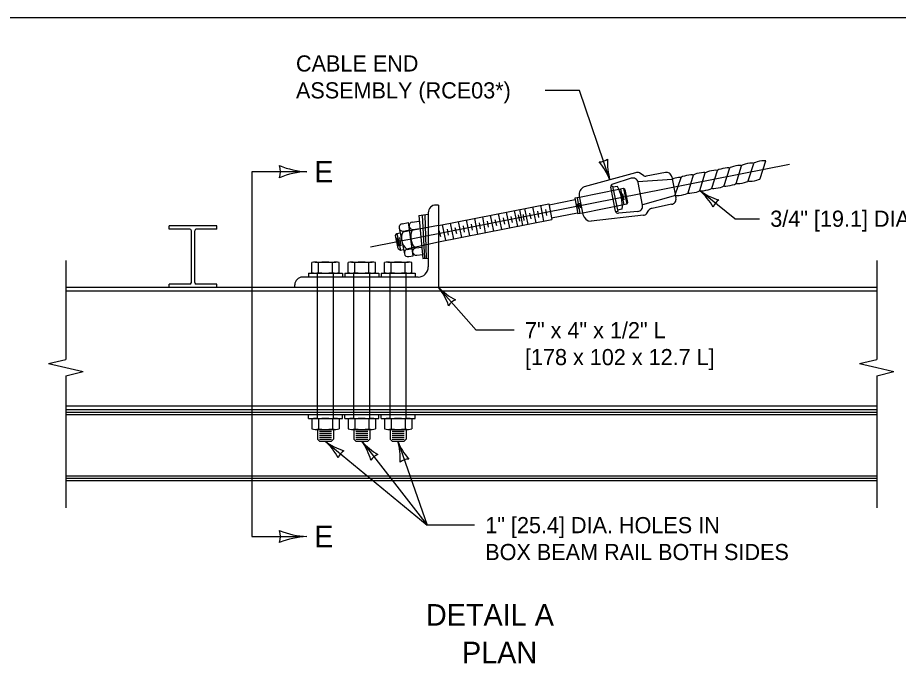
# Model space of a CAD drawing. Extents: x 49991.4 to 50021, y 49987.6 to 50011.4.
# Drawn here: x 50009.364 to 50012.637, y 49996.55 to 49998.999 of the extents above; entities that cross this region are included whole.
import ezdxf

# ---------------------------------------------------------------- set-up
doc = ezdxf.new("R2010")
doc.units = 0
for name, color, linetype in [('Level 1', 7, 'Continuous'), ('Level 2', 7, 'Continuous'), ('Level 3', 7, 'Continuous'), ('Level 4', 7, 'Continuous'), ('Level 5', 7, 'Continuous'), ('Level 6', 7, 'Continuous')]:
    doc.layers.add(name, color=color, linetype=linetype)

msp = doc.modelspace()

# ---------------------------------------------------------------- linework, layer by layer
at = {"layer": 'Level 1'}
for p, q in [((50012.1234, 49998.4006), (50012.1441, 49998.466)), ((50011.9434, 49998.3651), (50011.9639, 49998.4304)), ((50012.0091, 49998.4397), (50011.9884, 49998.3739)), ((50012.0334, 49998.3828), (50012.0541, 49998.4482)), ((50012.0784, 49998.3917), (50012.0991, 49998.4571)), ((50011.6593, 49998.4216), (50011.4693, 49998.3696)), ((50011.6436, 49998.4017), (50011.575, 49998.3804)), ((50011.6913, 49998.4111), (50011.6747, 49998.4222)), ((50011.7707, 49998.4233), (50011.6991, 49998.409)), ((50011.7944, 49998.4073), (50011.81, 49998.3285)), ((50011.8077, 49998.3399), (50011.829, 49998.4042)), ((50011.8738, 49998.4134), (50011.8537, 49998.3469)), ((50011.8984, 49998.3562), (50011.9192, 49998.422)), ((50011.5748, 49998.3728), (50011.5679, 49998.3714)), ((50011.5859, 49998.2796), (50011.5681, 49998.3689)), ((50011.5748, 49998.3728), (50011.5943, 49998.2787)), ((50011.593, 49998.3717), (50011.5757, 49998.3683)), ((50011.6156, 49998.3632), (50011.5984, 49998.3598)), ((50011.6199, 49998.3603), (50011.6156, 49998.3632)), ((50011.6156, 49998.3632), (50011.6281, 49998.3051)), ((50011.686, 49998.302), (50011.6693, 49998.3864)), ((50011.4516, 49998.3307), (50011.4348, 49998.3274)), ((50011.4506, 49998.3356), (50011.4647, 49998.2666)), ((50011.6038, 49998.3607), (50011.6163, 49998.3029)), ((50011.6121, 49998.3441), (50011.617, 49998.3212)), ((50011.6199, 49998.3603), (50011.6306, 49998.3111)), ((50010.9279, 49998.3022), (50010.9183, 49998.3022)), ((50010.9279, 49998.2263), (50011.3373, 49998.3072)), ((50010.9279, 49998.3022), (50010.9279, 49997.9962)), ((50011.3068, 49998.3012), (50011.3185, 49998.242)), ((50011.3373, 49998.3072), (50011.3489, 49998.2481)), ((50011.4358, 49998.322), (50011.3384, 49998.3018)), ((50011.4348, 49998.3274), (50011.4454, 49998.269)), ((50011.4433, 49998.3077), (50011.448, 49998.289)), ((50011.4544, 49998.2708), (50011.4438, 49998.3292)), ((50011.4523, 49998.3094), (50011.4558, 49998.2915)), ((50011.6281, 49998.3051), (50011.6108, 49998.3017)), ((50011.6306, 49998.3111), (50011.6281, 49998.3051)), ((50011.7941, 49998.3049), (50011.7219, 49998.2898)), ((50010.8544, 49998.2636), (50010.8897, 49998.2678)), ((50010.8666, 49998.265), (50010.8756, 49998.1039)), ((50010.8776, 49998.2663), (50010.8824, 49998.1041)), ((50010.8898, 49998.2737), (50010.8898, 49998.0724)), ((50010.8898, 49998.2678), (50010.8898, 49998.1043)), ((50011.15, 49998.2702), (50011.1616, 49998.211)), ((50011.1795, 49998.276), (50011.1912, 49998.2169)), ((50011.2091, 49998.2819), (50011.2217, 49998.2229)), ((50011.2236, 49998.2652), (50011.2282, 49998.2419)), ((50011.2288, 49998.2858), (50011.2396, 49998.2265)), ((50011.2418, 49998.2669), (50011.2454, 49998.2444)), ((50011.2477, 49998.2895), (50011.2593, 49998.2303)), ((50011.2659, 49998.2726), (50011.2712, 49998.2504)), ((50011.2772, 49998.2953), (50011.2898, 49998.2364)), ((50011.2953, 49998.2793), (50011.2999, 49998.256)), ((50011.3258, 49998.2853), (50011.3293, 49998.2628)), ((50011.4448, 49998.2726), (50011.3479, 49998.2534)), ((50011.4635, 49998.2726), (50011.4454, 49998.269)), ((50011.5943, 49998.2787), (50011.5866, 49998.2772)), ((50011.6106, 49998.2867), (50011.5934, 49998.2833)), ((50011.668, 49998.2781), (50011.5967, 49998.2715)), ((50011.7004, 49998.2694), (50011.7096, 49998.283)), ((50010.7924, 49998.2322), (50010.8167, 49998.237)), ((50010.8333, 49998.1138), (50010.8167, 49998.237)), ((50010.8303, 49998.2387), (50010.8564, 49998.2422)), ((50010.8544, 49998.2636), (50010.8692, 49998.1037)), ((50010.9279, 49998.1648), (50011.3489, 49998.2481)), ((50010.9716, 49998.235), (50010.9833, 49998.1758)), ((50011.0012, 49998.2408), (50011.0137, 49998.1818)), ((50011.0307, 49998.2466), (50011.0424, 49998.1875)), ((50011.0612, 49998.2527), (50011.0729, 49998.1935)), ((50011.0784, 49998.2365), (50011.083, 49998.2132)), ((50011.0908, 49998.2585), (50011.1016, 49998.1992)), ((50011.1089, 49998.2425), (50011.1124, 49998.22)), ((50011.1204, 49998.2643), (50011.1321, 49998.2052)), ((50011.1375, 49998.2482), (50011.1429, 49998.2259)), ((50011.168, 49998.2542), (50011.1726, 49998.2309)), ((50011.1967, 49998.2599), (50011.202, 49998.2377)), ((50011.6894, 49998.2646), (50011.4946, 49998.2422)), ((50010.1047, 49998.2248), (50009.9271, 49998.2248)), ((50009.9271, 49998.2128), (50009.9271, 49998.2248)), ((50010.0039, 49998.2128), (50009.9271, 49998.2128)), ((50010.0099, 49998.0142), (50010.0099, 49998.2068)), ((50010.0219, 49998.0142), (50010.0219, 49998.2068)), ((50010.1047, 49998.2128), (50010.0279, 49998.2128)), ((50010.1047, 49998.2128), (50010.1047, 49998.2248)), ((50010.7816, 49998.2161), (50010.8009, 49998.1213)), ((50010.7977, 49998.2054), (50010.8204, 49998.2098)), ((50010.834, 49998.2116), (50010.8589, 49998.2149)), ((50010.9296, 49998.2071), (50010.9349, 49998.1849)), ((50010.942, 49998.2291), (50010.9537, 49998.17)), ((50010.96, 49998.2131), (50010.9636, 49998.1905)), ((50010.9887, 49998.2188), (50010.9941, 49998.1965)), ((50011.0192, 49998.2248), (50011.0238, 49998.2015)), ((50011.0497, 49998.2309), (50011.0532, 49998.2082)), ((50010.7683, 49998.1891), (50010.7733, 49998.1967)), ((50010.7778, 49998.1407), (50010.7683, 49998.1891)), ((50010.7733, 49998.1967), (50010.7851, 49998.199)), ((50010.7733, 49998.1967), (50010.7864, 49998.135)), ((50010.7807, 49998.1497), (50010.7736, 49998.1809)), ((50010.789, 49998.1504), (50010.7837, 49998.182)), ((50010.7778, 49998.1407), (50010.7864, 49998.135)), ((50010.7864, 49998.135), (50010.7977, 49998.1372)), ((50010.8117, 49998.1374), (50010.8296, 49998.141)), ((50010.8432, 49998.1428), (50010.8653, 49998.1457)), ((50010.817, 49998.1105), (50010.8333, 49998.1138)), ((50010.8468, 49998.1156), (50010.8678, 49998.1184)), ((50010.8692, 49998.1037), (50010.8898, 49998.1043)), ((50010.457, 49998.0514), (50010.457, 49998.088)), ((50010.4698, 49998.0902), (50010.5458, 49998.0902)), ((50010.4822, 49998.0513), (50010.4822, 49998.0881)), ((50010.5334, 49998.0513), (50010.5334, 49998.0881)), ((50010.5586, 49998.0514), (50010.5586, 49998.088)), ((50010.592, 49998.0514), (50010.592, 49998.088)), ((50010.6048, 49998.0902), (50010.6808, 49998.0902)), ((50010.6172, 49998.0513), (50010.6172, 49998.0881)), ((50010.6684, 49998.0513), (50010.6684, 49998.0881)), ((50010.6936, 49998.0514), (50010.6936, 49998.088)), ((50010.727, 49998.0514), (50010.727, 49998.088)), ((50010.7398, 49998.0902), (50010.8158, 49998.0902)), ((50010.7522, 49998.0513), (50010.7522, 49998.0881)), ((50010.8034, 49998.0513), (50010.8034, 49998.0881)), ((50010.8286, 49998.0514), (50010.8286, 49998.088)), ((50010.445, 49998.0493), (50010.5708, 49998.0493)), ((50010.445, 49998.0493), (50010.445, 49998.0343)), ((50010.5708, 49998.0493), (50010.5708, 49998.0343)), ((50010.58, 49998.0493), (50010.7058, 49998.0493)), ((50010.58, 49998.0493), (50010.58, 49998.0343)), ((50010.7058, 49998.0493), (50010.7058, 49998.0343)), ((50010.715, 49998.0493), (50010.8408, 49998.0493)), ((50010.715, 49998.0493), (50010.715, 49998.0343)), ((50010.8408, 49998.0493), (50010.8408, 49998.0343)), ((50010.0039, 49998.0082), (50009.9271, 49998.0082)), ((50009.9271, 49997.9962), (50009.9271, 49998.0082)), ((50010.1047, 49998.0082), (50010.0279, 49998.0082)), ((50010.1047, 49997.9962), (50010.1047, 49998.0082)), ((50010.3939, 49997.9962), (50010.3939, 49998.0058)), ((50010.8517, 49998.0343), (50010.4224, 49998.0343)), ((50012.556, 49997.9962), (50009.543, 49997.9962)), ((50012.556, 49997.5402), (50009.543, 49997.5402)), ((50012.556, 49997.2762), (50009.543, 49997.2762))]:
    msp.add_line(p, q, dxfattribs=at)
msp.add_lwpolyline([(49999.3835, 49998.9992), (50016.7501, 49998.9992), (50016.7501, 49987.7988), (49999.3835, 49987.7988)], close=True, dxfattribs=at)
for centre, radius, start, end in [((50011.6496, 49998.3825), 0.0202, 11.1741, 107.0803), ((50011.6679, 49998.3994), 0.0239, 73.4581, 110.9758), ((50011.6977, 49998.4192), 0.0103, 231.8958, 277.7889), ((50011.7752, 49998.4044), 0.0194, 8.5896, 103.4983), ((50011.4802, 49998.3415), 0.0302, 111.2677, 191.1741), ((50011.578, 49998.3708), 0.0101, 107.1508, 191.0424), ((50011.4409, 49998.2958), 0.17, 356.9288, 26.5077), ((50010.9183, 49998.2737), 0.0285, 90, 180), ((50011.6661, 49998.2982), 0.0203, 275.5759, 10.819), ((50011.7911, 49998.3241), 0.0194, 278.7928, 13.2099), ((50011.4943, 49998.2725), 0.0302, 191.1741, 270.5545), ((50011.5958, 49998.2815), 0.0101, 191.0393, 275.2819), ((50011.6887, 49998.2811), 0.0165, 272.4861, 314.9673), ((50011.7233, 49998.2727), 0.0171, 94.4838, 142.9949), ((50010.795, 49998.2188), 0.0137, 101.0862, 281.2575), ((50010.8322, 49998.2252), 0.0137, 97.6335, 277.6306), ((50010.0039, 49998.2068), 0.006, 0, 90), ((50010.0279, 49998.2068), 0.006, 90, 180), ((50010.841, 49998.1789), 0.0508, 148.6017, 234.753), ((50010.8848, 49998.1833), 0.0602, 152.0655, 223.0482), ((50010.8144, 49998.124), 0.0137, 101.2848, 281.0635), ((50010.845, 49998.1292), 0.0137, 97.6585, 277.6455), ((50010.8517, 49998.0724), 0.0381, 270, 0), ((50010.0039, 49998.0142), 0.006, 270, 0), ((50010.0279, 49998.0142), 0.006, 180, 270), ((50010.4224, 49998.0058), 0.0285, 90, 180)]:
    msp.add_arc(centre, radius, start, end, dxfattribs=at)
for centre, major_axis, ratio, start_param, end_param in [((50012.1216, 49998.4616), (-0.0225, -0.0044), 0.155406, 3.141593, 6.283185), ((50011.9414, 49998.4257), (-0.0225, -0.0044), 0.155406, 3.190469, 6.091551), ((50011.9866, 49998.4349), (-0.0227, -0.0045), 0.153923, 3.240033, 6.283185), ((50012.0316, 49998.4438), (-0.0225, -0.0044), 0.155406, 3.141593, 6.185749), ((50012.0766, 49998.4527), (-0.0225, -0.0044), 0.155406, 3.142586, 6.283185), ((50011.8125, 49998.4008), (0.0165, 0.0034), 0.140692, 0, 2.948999), ((50011.8515, 49998.4086), (-0.0225, -0.0044), 0.155406, 3.234173, 6.283185), ((50011.8965, 49998.4175), (-0.0227, -0.0045), 0.15408, 3.144636, 6.190605), ((50012.1009, 49998.3962), (0.0225, 0.0044), 0.155406, 3.141593, 6.283185), ((50011.9209, 49998.3606), (0.0225, 0.0044), 0.155406, 3.141593, 6.283185), ((50011.9659, 49998.3695), (0.0225, 0.0044), 0.155406, 3.141593, 6.283185), ((50012.0109, 49998.3784), (0.0225, 0.0044), 0.155406, 3.141593, 6.283185), ((50012.0559, 49998.3873), (0.0225, 0.0044), 0.155406, 3.141593, 6.283185), ((50011.8309, 49998.3428), (0.0229, 0.0045), 0.153003, 3.141593, 6.158276), ((50011.8759, 49998.3517), (0.0225, 0.0044), 0.155406, 3.266502, 6.283185), ((50010.4697, 49998.0743), (0.0254, 0), 0.623816, 1.056847, 2.094396), ((50010.5078, 49998.0268), (0.1016, 0), 0.623816, 1.315951, 1.825641), ((50010.5459, 49998.0743), (0.0254, 0), 0.623816, 1.047198, 2.084746), ((50010.6047, 49998.0743), (0.0254, 0), 0.623816, 1.056847, 2.094396), ((50010.6428, 49998.0268), (0.1016, 0), 0.623816, 1.315951, 1.825641), ((50010.6809, 49998.0743), (0.0254, 0), 0.623816, 1.047198, 2.084746), ((50010.7397, 49998.0743), (0.0254, 0), 0.623816, 1.056847, 2.094396), ((50010.7778, 49998.0268), (0.1016, 0), 0.623816, 1.315951, 1.825641), ((50010.8159, 49998.0743), (0.0254, 0), 0.623816, 1.047198, 2.084746), ((50010.4697, 49998.0651), (0.0254, 0), 0.623816, 4.188789, 5.226338), ((50010.5078, 49998.1126), (0.1016, 0), 0.623816, 4.457545, 4.967235), ((50010.5459, 49998.0651), (0.0254, 0), 0.623816, 4.198439, 5.235988), ((50010.6047, 49998.0651), (0.0254, 0), 0.623816, 4.188789, 5.226338), ((50010.6428, 49998.1126), (0.1016, 0), 0.623816, 4.457545, 4.967235), ((50010.6809, 49998.0651), (0.0254, 0), 0.623816, 4.198439, 5.235988), ((50010.7397, 49998.0651), (0.0254, 0), 0.623816, 4.188789, 5.226338), ((50010.7778, 49998.1126), (0.1016, 0), 0.623816, 4.457545, 4.967235), ((50010.8159, 49998.0651), (0.0254, 0), 0.623816, 4.198439, 5.235988)]:
    msp.add_ellipse(centre, major_axis=major_axis, ratio=ratio, start_param=start_param, end_param=end_param, dxfattribs=at)
at = {"layer": 'Level 3'}
for p, q in [((50011.4516, 49998.7287), (50011.3245, 49998.7287)), ((50011.5648, 49998.3958), (50011.4516, 49998.7287)), ((50012.0292, 49998.2514), (50011.8995, 49998.3553)), ((50012.0292, 49998.2514), (50012.1205, 49998.2514)), ((50011.0672, 49997.8368), (50010.9279, 49997.9962)), ((50011.2091, 49997.8368), (50011.0672, 49997.8368)), ((50010.5069, 49997.424), (50010.8851, 49997.112)), ((50010.6431, 49997.424), (50010.8851, 49997.112)), ((50010.7763, 49997.424), (50010.8851, 49997.112)), ((50011.0616, 49997.112), (50010.8851, 49997.112))]:
    msp.add_line(p, q, dxfattribs=at)
for centre, radius, start, end in [((50011.5235, 49998.5172), 0.0548, 270.9069, 306.6293), ((50011.3574, 49998.3156), 0.2223, 21.1286, 41.3121), ((50011.7888, 49998.4598), 0.233, 176.691, 195.9408), ((50012.0308, 49998.5347), 0.2223, 233.7575, 253.941), ((50011.7452, 49998.1807), 0.233, 29.3199, 48.5697), ((50011.9995, 49998.2754), 0.0548, 123.5359, 159.2582), ((50010.7546, 49997.8569), 0.2223, 18.6103, 38.7938), ((50011.0955, 49998.158), 0.233, 223.9816, 243.2315), ((50011.0122, 49997.8997), 0.0548, 113.2931, 149.0155), ((50010.6412, 49997.6012), 0.2223, 232.8407, 253.0242), ((50010.3499, 49997.2518), 0.233, 28.403, 47.6529), ((50010.813, 49997.5674), 0.2223, 220.1612, 240.3448), ((50010.4522, 49997.2905), 0.233, 15.7236, 34.9735), ((50010.9831, 49997.5058), 0.2223, 201.5833, 221.7668), ((50010.5528, 49997.3583), 0.233, 357.1456, 16.3955), ((50010.6058, 49997.3425), 0.0548, 122.619, 158.3414), ((50010.7217, 49997.3227), 0.0548, 109.9396, 145.6619), ((50010.8185, 49997.303), 0.0548, 91.3616, 127.084)]:
    msp.add_arc(centre, radius, start, end, dxfattribs=at)
at = {"layer": 'Level 4'}
for p, q in [((50011.7964, 49998.3974), (50011.6687, 49998.3888)), ((50011.5984, 49998.3598), (50011.4516, 49998.3307)), ((50011.8082, 49998.3374), (50011.6859, 49998.3024)), ((50011.6108, 49998.3017), (50011.4635, 49998.2726)), ((50010.9279, 49998.2263), (50010.7953, 49998.201)), ((50010.8087, 49998.1397), (50010.9279, 49998.1648)), ((50010.4778, 49997.5087), (50010.4778, 49998.0493)), ((50010.5378, 49997.5087), (50010.5378, 49998.0493)), ((50010.6128, 49997.5087), (50010.6128, 49998.0493)), ((50010.6728, 49997.5087), (50010.6728, 49998.0493)), ((50010.7478, 49997.5087), (50010.7478, 49998.0493)), ((50010.8078, 49997.5087), (50010.8078, 49998.0493)), ((50012.556, 49997.9818), (50009.543, 49997.9818)), ((50012.556, 49997.5546), (50009.543, 49997.5546)), ((50012.556, 49997.5311), (50009.543, 49997.5311)), ((50012.556, 49997.522), (50009.543, 49997.522)), ((50010.445, 49997.5087), (50010.445, 49997.522)), ((50010.5708, 49997.5087), (50010.5708, 49997.522)), ((50010.58, 49997.5087), (50010.58, 49997.522)), ((50010.7058, 49997.5087), (50010.7058, 49997.522)), ((50010.715, 49997.5087), (50010.715, 49997.522)), ((50010.8408, 49997.5087), (50010.8408, 49997.522)), ((50010.445, 49997.5087), (50010.5708, 49997.5087)), ((50010.457, 49997.5066), (50010.457, 49997.4699)), ((50010.4821, 49997.5067), (50010.4821, 49997.4698)), ((50010.5335, 49997.5067), (50010.5335, 49997.4699)), ((50010.5586, 49997.5066), (50010.5586, 49997.4699)), ((50010.58, 49997.5087), (50010.7058, 49997.5087)), ((50010.592, 49997.5066), (50010.592, 49997.4699)), ((50010.6171, 49997.5066), (50010.6171, 49997.4699)), ((50010.6685, 49997.5067), (50010.6685, 49997.4699)), ((50010.6936, 49997.5066), (50010.6936, 49997.4699)), ((50010.715, 49997.5087), (50010.8408, 49997.5087)), ((50010.727, 49997.5066), (50010.727, 49997.4699)), ((50010.7522, 49997.5067), (50010.7522, 49997.4699)), ((50010.8035, 49997.5067), (50010.8035, 49997.4698)), ((50010.8286, 49997.5066), (50010.8286, 49997.4699)), ((50010.4698, 49997.4678), (50010.5458, 49997.4678)), ((50010.4778, 49997.4678), (50010.4778, 49997.4315)), ((50010.4853, 49997.4615), (50010.5303, 49997.4615)), ((50010.4853, 49997.454), (50010.5303, 49997.454)), ((50010.4853, 49997.4465), (50010.5303, 49997.4465)), ((50010.5378, 49997.4678), (50010.5378, 49997.4315)), ((50010.6048, 49997.4678), (50010.6808, 49997.4678)), ((50010.6128, 49997.4678), (50010.6128, 49997.4315)), ((50010.6203, 49997.4615), (50010.6653, 49997.4615)), ((50010.6203, 49997.454), (50010.6653, 49997.454)), ((50010.6203, 49997.4465), (50010.6653, 49997.4465)), ((50010.6728, 49997.4678), (50010.6728, 49997.4315)), ((50010.7398, 49997.4678), (50010.8158, 49997.4678)), ((50010.7478, 49997.4678), (50010.7478, 49997.4315)), ((50010.7553, 49997.4615), (50010.8003, 49997.4615)), ((50010.7553, 49997.454), (50010.8003, 49997.454)), ((50010.7553, 49997.4465), (50010.8003, 49997.4465)), ((50010.8078, 49997.4678), (50010.8078, 49997.4315)), ((50010.4778, 49997.4315), (50010.4853, 49997.424)), ((50010.4853, 49997.439), (50010.5303, 49997.439)), ((50010.4853, 49997.4315), (50010.5303, 49997.4315)), ((50010.4853, 49997.424), (50010.5303, 49997.424)), ((50010.5378, 49997.4315), (50010.5303, 49997.424)), ((50010.6128, 49997.4315), (50010.6203, 49997.424)), ((50010.6203, 49997.439), (50010.6653, 49997.439)), ((50010.6203, 49997.4315), (50010.6653, 49997.4315)), ((50010.6203, 49997.424), (50010.6653, 49997.424)), ((50010.6728, 49997.4315), (50010.6653, 49997.424)), ((50010.7478, 49997.4315), (50010.7553, 49997.424)), ((50010.7553, 49997.439), (50010.8003, 49997.439)), ((50010.7553, 49997.4315), (50010.8003, 49997.4315)), ((50010.7553, 49997.424), (50010.8003, 49997.424)), ((50010.8078, 49997.4315), (50010.8003, 49997.424)), ((50012.556, 49997.2944), (50009.543, 49997.2944)), ((50012.556, 49997.2853), (50009.543, 49997.2853))]:
    msp.add_line(p, q, dxfattribs=at)
for centre, major_axis, start_param, end_param in [((50010.4697, 49997.4929), (0.0254, 0), 1.056847, 2.094396), ((50010.5078, 49997.4453), (0.1016, 0), 1.31595, 1.825641), ((50010.5459, 49997.4929), (0.0254, 0), 1.047198, 2.084746), ((50010.6047, 49997.4929), (0.0254, 0), 1.056847, 2.094396), ((50010.6428, 49997.4453), (0.1016, 0), 1.31595, 1.825641), ((50010.6809, 49997.4929), (0.0254, 0), 1.047198, 2.084746), ((50010.7397, 49997.4929), (0.0254, 0), 1.056847, 2.094396), ((50010.7778, 49997.4453), (0.1016, 0), 1.31595, 1.825641), ((50010.8159, 49997.4929), (0.0254, 0), 1.047198, 2.084746), ((50010.4697, 49997.4837), (0.0254, 0), 4.188789, 5.226338), ((50010.5078, 49997.5312), (0.1016, 0), 4.457545, 4.967234), ((50010.5459, 49997.4837), (0.0254, 0), 4.198439, 5.235988), ((50010.6047, 49997.4837), (0.0254, 0), 4.188789, 5.226338), ((50010.6428, 49997.5312), (0.1016, 0), 4.457545, 4.967234), ((50010.6809, 49997.4837), (0.0254, 0), 4.198439, 5.235988), ((50010.7397, 49997.4837), (0.0254, 0), 4.188789, 5.226338), ((50010.7778, 49997.5312), (0.1016, 0), 4.457545, 4.967234), ((50010.8159, 49997.4837), (0.0254, 0), 4.198439, 5.235988)]:
    msp.add_ellipse(centre, major_axis=major_axis, ratio=0.623816, start_param=start_param, end_param=end_param, dxfattribs=at)
at = {"layer": 'Level 5'}
msp.add_line((50012.2321, 49998.4534), (50010.6749, 49998.1458), dxfattribs=at)
at = {"layer": 'Level 6'}
for p, q in [((50010.4134, 49998.4263), (50010.2347, 49998.4263)), ((50010.2347, 49998.4263), (50010.2347, 49997.0696)), ((50009.543, 49998.0962), (50009.543, 49997.728)), ((50012.556, 49998.0962), (50012.556, 49997.728)), ((50009.4792, 49997.7131), (50009.543, 49997.728)), ((50009.4792, 49997.7131), (50009.543, 49997.6978)), ((50012.4922, 49997.7131), (50012.556, 49997.728)), ((50012.4922, 49997.7131), (50012.556, 49997.6978)), ((50009.543, 49997.6978), (50009.6071, 49997.6827)), ((50009.543, 49997.6674), (50009.6071, 49997.6827)), ((50012.556, 49997.6978), (50012.6201, 49997.6827)), ((50012.556, 49997.6674), (50012.6201, 49997.6827)), ((50009.543, 49997.6674), (50009.543, 49997.1762)), ((50012.556, 49997.6674), (50012.556, 49997.1762)), ((50010.2347, 49997.0696), (50010.4134, 49997.0696))]:
    msp.add_line(p, q, dxfattribs=at)
for centre, radius, start, end in [((50010.2677, 49998.4263), 0.073, 342.1388, 17.8612), ((50010.454, 49998.7366), 0.3107, 247.9228, 267.1727), ((50010.4508, 49998.1301), 0.2964, 92.3605, 112.544), ((50010.2677, 49997.0696), 0.073, 342.1388, 17.8612), ((50010.454, 49997.3799), 0.3107, 247.9228, 267.1727), ((50010.4508, 49996.7734), 0.2964, 92.3605, 112.544)]:
    msp.add_arc(centre, radius, start, end, dxfattribs=at)

# ---------------------------------------------------------------- texts
at = {"layer": 'Level 2'}
for s, p in [('CABLE END ', (50010.3983, 49998.7987)), ('ASSEMBLY (RCE03*)', (50010.3983, 49998.6987))]:
    msp.add_text(s, height=0.06, rotation=360, dxfattribs=at).set_placement(p)
for s, height, p in [('E', 0.08, (50010.4659, 49998.3863)), ('3/4" [19.1] DIA. CABLE (RCM01*)', 0.06, (50012.1605, 49998.2214)), ('7" x 4" x 1/2" L', 0.06, (50011.2491, 49997.8068)), ('[178 x 102 x 12.7 L]', 0.06, (50011.2491, 49997.7068)), ('1" [25.4] DIA. HOLES IN', 0.06, (50011.1016, 49997.082)), ('E', 0.08, (50010.4659, 49997.0296)), ('BOX BEAM RAIL BOTH SIDES', 0.06, (50011.1016, 49996.982)), ('DETAIL A', 0.08, (50010.8811, 49996.7384)), ('PLAN', 0.08, (50011.0151, 49996.5984))]:
    msp.add_text(s, height=height, dxfattribs=at).set_placement(p)

doc.saveas('drawing.dxf')
